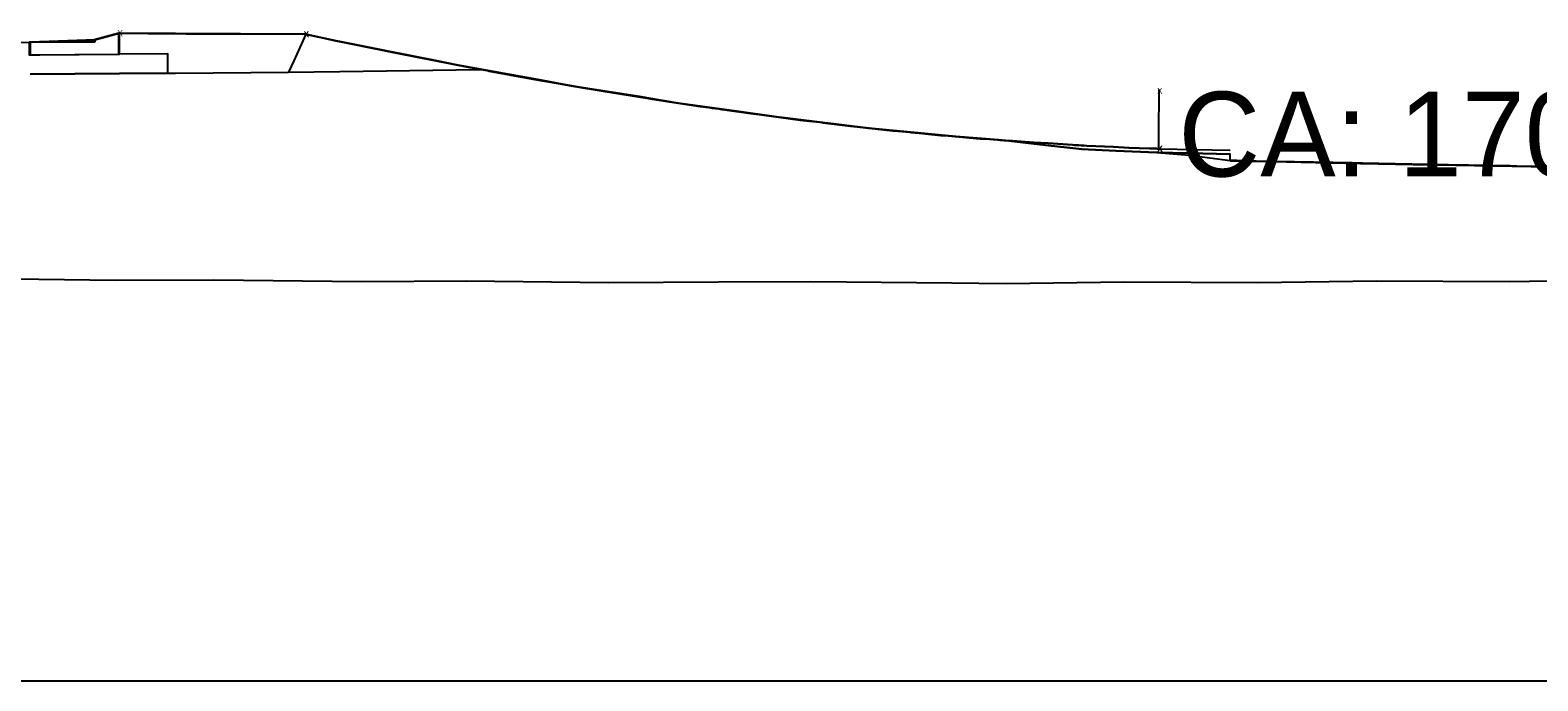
# Model space of a CAD drawing. Extents: x -26 to 303, y -16 to 6048.
# Drawn here: x 183.3 to 243, y 5500 to 5525.8 of the extents above; entities that cross this region are included whole.
import ezdxf

# ---------------------------------------------------------------- set-up
doc = ezdxf.new("R2010")
doc.units = 0
for name, color, linetype in [('CONST_DCH', 7, 'Continuous'), ('CONST_LV3', 7, 'Continuous'), ('DTM_P_FINISHED_GRADE2', 7, 'Continuous'), ('DTM_TEMP_DROP', 7, 'Continuous'), ('DTM_X_GROUND', 7, 'Continuous'), ('TRANS_EOP_PAVED', 7, 'Continuous'), ('X_PROFILES_1', 7, 'Continuous'), ('XS_CELL', 7, 'Continuous'), ('XS_M_SHAPES_EARTHWORK', 7, 'Continuous'), ('XS_P_CONCRETE', 7, 'Continuous'), ('XS_P_GROUND', 7, 'Continuous'), ('XS_P_SHOULDER', 7, 'Continuous'), ('XS_P_SUBGRADE_GRANULAR', 7, 'Continuous'), ('XS_P_SUBGRADE_GRANULAR_B', 7, 'Continuous'), ('XS_SHEET_EW_TX_AREA', 7, 'Continuous')]:
    doc.layers.add(name, color=color, linetype=linetype)

msp = doc.modelspace()

# ---------------------------------------------------------------- linework, layer by layer
at = {"layer": 'CONST_LV3'}
for points in [[(183.216, 5525.326), (183.216, 5524.826), (183.641, 5524.828), (186.773, 5524.85), (186.773, 5525.683), (185.796, 5525.426), (185.794, 5525.342), (183.641, 5525.328), (183.216, 5525.326)], [(186.773, 5525.683), (188.834, 5525.668), (188.862, 5525.668), (188.936, 5525.667), (188.956, 5525.667), (189.005, 5525.667), (189.009, 5525.667), (189.017, 5525.667), (189.153, 5525.666), (189.448, 5525.664), (190.441, 5525.658), (191.471, 5525.651), (194.17, 5525.641)], [(186.773, 5525.683), (188.834, 5525.668), (188.862, 5525.668), (188.936, 5525.667), (188.956, 5525.667), (189.005, 5525.667), (189.009, 5525.667), (189.017, 5525.667), (189.153, 5525.666), (189.448, 5525.664), (190.441, 5525.658), (191.471, 5525.651), (194.17, 5525.641), (195.275, 5525.404), (195.317, 5525.396), (195.435, 5525.372), (195.436, 5525.371), (195.522, 5525.354), (195.524, 5525.354), (195.539, 5525.35), (195.539, 5525.35), (195.898, 5525.275), (195.905, 5525.274), (197.735, 5524.899), (197.803, 5524.888), (200.693, 5524.322), (200.892, 5524.29), (201.015, 5524.266), (201.024, 5524.265), (201.117, 5524.247), (201.124, 5524.246), (201.141, 5524.243), (201.142, 5524.243), (201.437, 5524.187), (201.46, 5524.183), (203.043, 5523.89), (203.196, 5523.866), (205.501, 5523.46), (205.789, 5523.42), (205.915, 5523.398), (205.931, 5523.396), (206.029, 5523.38), (206.042, 5523.378), (206.059, 5523.375), (206.061, 5523.375), (206.081, 5523.372), (206.084, 5523.371), (206.312, 5523.332), (206.344, 5523.328), (207.718, 5523.101), (207.928, 5523.073), (209.834, 5522.776), (210.173, 5522.735), (210.3, 5522.716), (210.324, 5522.713), (210.443, 5522.696), (210.465, 5522.694), (210.485, 5522.691), (210.489, 5522.69), (210.683, 5522.661), (210.72, 5522.657), (211.928, 5522.482), (212.175, 5522.454), (213.797, 5522.236), (214.164, 5522.199), (214.293, 5522.183), (214.323, 5522.18), (214.445, 5522.164), (214.474, 5522.162), (214.663, 5522.138), (214.708, 5522.133), (215.787, 5522), (216.056, 5521.976), (217.474, 5521.816), (217.854, 5521.785), (217.985, 5521.771), (218.021, 5521.769), (218.129, 5521.757), (218.159, 5521.755), (218.177, 5521.754), (218.182, 5521.753), (218.202, 5521.751), (218.208, 5521.751), (218.358, 5521.735), (218.4, 5521.732), (219.379, 5521.632), (219.661, 5521.612), (220.93, 5521.497), (221.314, 5521.475), (221.448, 5521.463), (221.49, 5521.461), (221.62, 5521.45), (221.66, 5521.448), (221.662, 5521.448), (221.662, 5521.448), (221.711, 5521.445), (221.866, 5521.432), (222.202, 5521.414), (223.059, 5521.346), (223.627, 5521.319), (224.601, 5521.252), (224.673, 5521.249), (224.787, 5521.242), (224.85, 5521.24), (224.944, 5521.234), (224.954, 5521.234), (224.968, 5521.233), (225.05, 5521.229), (225.165, 5521.222), (226.224, 5521.176), (226.833, 5521.143), (227.664, 5521.114), (227.764, 5521.109), (227.845, 5521.107), (227.851, 5521.107), (227.927, 5521.104), (227.93, 5521.104), (227.942, 5521.104), (227.943, 5521.104), (227.956, 5521.103), (227.957, 5521.103), (228.018, 5521.101)], [(186.798, 5525.683), (189.017, 5525.667), (194.193, 5525.642), (195.32, 5525.395), (195.539, 5525.35), (200.238, 5524.411), (201.142, 5524.243), (204.774, 5523.588), (206.061, 5523.375), (208.964, 5522.91), (210.465, 5522.693), (212.859, 5522.361), (214.474, 5522.162), (216.512, 5521.923), (218.182, 5521.753), (219.967, 5521.583), (221.66, 5521.448), (221.803, 5521.436), (221.947, 5521.426), (223.523, 5521.24), (224.968, 5521.086), (226.308, 5521.018), (227.943, 5520.957), (229.217, 5520.92), (230.846, 5520.892)], [(188.722, 5524.094), (188.723, 5524.865), (186.798, 5524.85)], [(228.048, 5521.101), (230.838, 5521.039), (230.844, 5521.039), (230.846, 5521.039)]]:
    msp.add_lwpolyline(points, dxfattribs=at)
at = {"layer": 'DTM_P_FINISHED_GRADE2'}
msp.add_lwpolyline([(180.574, 5525.313), (183.26, 5525.327), (184.747, 5525.335), (185.827, 5525.343), (185.828, 5525.379), (185.829, 5525.426), (186.203, 5525.525), (186.798, 5525.683), (187.942, 5525.672), (189.017, 5525.667), (194.193, 5525.642), (195.32, 5525.395), (199.395, 5524.585), (200.238, 5524.411), (203.542, 5523.817), (204.774, 5523.588), (207.504, 5523.153), (208.964, 5522.91), (211.268, 5522.591), (212.859, 5522.361), (214.474, 5522.162), (216.512, 5521.923), (218.182, 5521.753), (219.967, 5521.583), (220.109, 5521.572), (221.803, 5521.436), (221.947, 5521.426), (223.523, 5521.24), (224.968, 5521.086), (226.308, 5521.018), (227.943, 5520.957), (229.23, 5520.84), (230.846, 5520.634), (230.926, 5520.633), (231.048, 5520.63), (231.236, 5520.627), (231.341, 5520.625), (231.628, 5520.619), (231.875, 5520.614), (232.987, 5520.593), (235.685, 5520.54), (235.76, 5520.539), (235.8, 5520.538), (235.99, 5520.534), (236.09, 5520.532), (236.825, 5520.518), (238.697, 5520.482), (238.919, 5520.478), (239.144, 5520.474), (239.719, 5520.462), (239.894, 5520.459), (240.481, 5520.448), (240.941, 5520.439), (241.113, 5520.436), (241.116, 5520.436), (241.217, 5520.434), (241.673, 5520.425), (241.744, 5520.424), (241.75, 5520.423), (242.022, 5520.418), (242.194, 5520.415), (242.385, 5520.411), (242.508, 5520.409), (242.971, 5520.4), (243.02, 5520.399), (243.352, 5520.393)], dxfattribs=at)
at = {"layer": 'DTM_X_GROUND'}
for points in [[(183.26, 5525.327), (184.748, 5525.383), (185.829, 5525.426), (186.462, 5525.595), (186.798, 5525.683), (187.942, 5525.672), (189.017, 5525.667), (194.193, 5525.642), (195.32, 5525.395), (199.395, 5524.585), (200.238, 5524.411), (203.542, 5523.817), (204.774, 5523.588), (207.504, 5523.153), (207.795, 5523.104), (208.964, 5522.91), (211.268, 5522.591), (212.859, 5522.361), (213.73, 5522.253), (214.474, 5522.162), (216.512, 5521.923), (216.908, 5521.883), (217.404, 5521.832), (218.182, 5521.753), (219.967, 5521.583), (220.109, 5521.572), (221.803, 5521.436), (221.947, 5521.426), (223.523, 5521.24), (224.968, 5521.086), (226.308, 5521.018), (227.322, 5520.98), (227.943, 5520.957), (229.23, 5520.84), (230.846, 5520.634), (230.926, 5520.633), (231.048, 5520.63), (231.107, 5520.629), (231.236, 5520.627), (231.341, 5520.625), (231.628, 5520.619), (231.644, 5520.619), (231.891, 5520.614), (231.929, 5520.613), (232.674, 5520.599), (234.47, 5520.564), (234.819, 5520.557), (235.685, 5520.54), (235.76, 5520.539), (235.8, 5520.538), (235.99, 5520.534), (236.251, 5520.529), (236.351, 5520.527), (237.01, 5520.515), (237.484, 5520.506), (237.866, 5520.498), (238.697, 5520.482), (238.919, 5520.478), (238.935, 5520.478), (239.111, 5520.474), (239.686, 5520.463), (239.719, 5520.462), (239.76, 5520.462), (239.902, 5520.459), (240.304, 5520.451), (240.361, 5520.45), (240.448, 5520.448), (240.481, 5520.448), (240.855, 5520.441), (240.996, 5520.438), (241.083, 5520.436), (241.113, 5520.436), (241.116, 5520.436), (241.49, 5520.428), (241.592, 5520.427), (241.631, 5520.426), (241.712, 5520.424), (241.718, 5520.424), (241.75, 5520.423), (242.022, 5520.418), (242.162, 5520.416), (242.266, 5520.414), (242.353, 5520.412), (242.385, 5520.411), (242.761, 5520.404), (242.884, 5520.402), (242.9, 5520.401), (242.987, 5520.4), (243.02, 5520.399), (243.352, 5520.393)], [(180.548, 5515.965), (186.639, 5515.888), (190.547, 5515.908), (196.408, 5515.838), (200.547, 5515.859), (206.192, 5515.795), (210.547, 5515.818), (214.225, 5515.837), (219.816, 5515.78), (221.959, 5515.757), (226.64, 5515.827), (231.941, 5515.797), (236.65, 5515.869), (241.923, 5515.837), (246.661, 5515.911)]]:
    msp.add_lwpolyline(points, dxfattribs=at)
at = {"layer": 'XS_CELL'}
msp.add_line((150, 5500), (300, 5500), dxfattribs=at)
at = {"layer": 'XS_M_SHAPES_EARTHWORK'}
msp.add_lwpolyline([(183.26, 5524.056), (186.798, 5524.079), (188.722, 5524.094), (189.017, 5524.097), (193.505, 5524.14), (195.539, 5524.163), (201.08, 5524.238), (201.142, 5524.238), (201.166, 5524.239), (204.774, 5523.588), (203.542, 5523.817), (200.238, 5524.411), (199.395, 5524.585), (195.32, 5525.395), (194.193, 5525.642), (189.017, 5525.667), (187.942, 5525.672), (186.798, 5525.683), (186.462, 5525.595), (185.829, 5525.426), (184.748, 5525.383), (183.26, 5525.327)], dxfattribs=at)
for points in [[(206.061, 5523.375), (208.964, 5522.91), (207.795, 5523.104), (207.504, 5523.153), (204.774, 5523.588)], [(210.465, 5522.693), (212.859, 5522.361), (211.268, 5522.591), (208.964, 5522.91)], [(219.967, 5521.583), (220.109, 5521.572), (221.803, 5521.436), (221.66, 5521.448)], [(227.943, 5520.957), (229.23, 5520.84), (230.846, 5520.634), (230.846, 5520.892), (229.217, 5520.92)]]:
    msp.add_lwpolyline(points, close=True, dxfattribs=at)
at = {"layer": 'XS_P_CONCRETE'}
msp.add_lwpolyline([(183.26, 5525.327), (183.26, 5524.827), (186.798, 5524.85), (186.798, 5525.683), (185.829, 5525.426), (185.827, 5525.343), (183.26, 5525.327)], dxfattribs=at)
at = {"layer": 'XS_P_GROUND'}
for points in [[(228.018, 5521.101), (227.957, 5521.103), (227.956, 5521.103), (227.943, 5521.104), (227.942, 5521.104), (227.93, 5521.104), (227.927, 5521.104), (227.851, 5521.107), (227.845, 5521.107), (227.764, 5521.109), (227.664, 5521.114), (226.833, 5521.143), (226.224, 5521.176), (225.165, 5521.222), (225.05, 5521.229), (224.968, 5521.233), (224.954, 5521.234), (224.944, 5521.234), (224.85, 5521.24), (224.787, 5521.242), (224.673, 5521.249), (224.601, 5521.252), (223.627, 5521.319), (223.059, 5521.346), (222.202, 5521.414), (221.866, 5521.432), (221.711, 5521.445), (221.662, 5521.448), (221.662, 5521.448), (221.66, 5521.448), (221.62, 5521.45), (221.49, 5521.461), (221.448, 5521.463), (221.314, 5521.475), (220.93, 5521.497), (219.661, 5521.612), (219.379, 5521.632), (218.4, 5521.732), (218.358, 5521.735), (218.208, 5521.751), (218.202, 5521.751), (218.182, 5521.753), (218.177, 5521.754), (218.159, 5521.755), (218.129, 5521.757), (218.021, 5521.769), (217.985, 5521.771), (217.854, 5521.785), (217.474, 5521.816), (216.056, 5521.976), (215.787, 5522), (214.708, 5522.133), (214.663, 5522.138), (214.474, 5522.162), (214.445, 5522.164), (214.323, 5522.18), (214.293, 5522.183), (214.164, 5522.199), (213.797, 5522.236), (212.175, 5522.454), (211.928, 5522.482), (210.72, 5522.657), (210.683, 5522.661), (210.489, 5522.69), (210.485, 5522.691), (210.465, 5522.694), (210.443, 5522.696), (210.324, 5522.713), (210.3, 5522.716), (210.173, 5522.735), (209.834, 5522.776), (207.928, 5523.073), (207.718, 5523.101), (206.344, 5523.328), (206.312, 5523.332), (206.084, 5523.371), (206.081, 5523.372), (206.061, 5523.375), (206.059, 5523.375), (206.042, 5523.378), (206.029, 5523.38), (205.931, 5523.396), (205.915, 5523.398), (205.789, 5523.42), (205.501, 5523.46), (203.196, 5523.866), (203.043, 5523.89), (201.46, 5524.183), (201.437, 5524.187), (201.142, 5524.243), (201.141, 5524.243), (201.124, 5524.246), (201.117, 5524.247), (201.024, 5524.265), (201.015, 5524.266), (200.892, 5524.29), (200.693, 5524.322), (197.803, 5524.888), (197.735, 5524.899), (195.905, 5525.274), (195.898, 5525.275), (195.539, 5525.35), (195.539, 5525.35), (195.524, 5525.354), (195.522, 5525.354), (195.436, 5525.371), (195.435, 5525.372), (195.317, 5525.396), (195.275, 5525.404), (194.17, 5525.641)], [(230.846, 5520.892), (229.217, 5520.92), (227.943, 5520.957), (226.308, 5521.018), (224.968, 5521.086), (223.523, 5521.24), (221.947, 5521.426), (221.803, 5521.436), (221.66, 5521.448), (219.967, 5521.583), (218.182, 5521.753), (216.512, 5521.923), (214.474, 5522.162), (212.859, 5522.361), (210.465, 5522.693), (208.964, 5522.91), (206.061, 5523.375), (204.774, 5523.588), (201.142, 5524.243), (200.238, 5524.411), (195.539, 5525.35), (195.32, 5525.395), (194.193, 5525.642)], [(228.018, 5521.101), (228.018, 5521.174), (228.022, 5521.7), (228.032, 5523.395), (228.032, 5523.398), (228.033, 5523.436), (228.048, 5523.436)], [(228.048, 5521.101), (230.838, 5521.039), (230.844, 5521.039), (230.846, 5521.039)], [(243.303, 5520.394), (242.848, 5520.402), (242.213, 5520.415), (241.95, 5520.42), (241.577, 5520.427), (241.569, 5520.427), (240.941, 5520.439), (240.306, 5520.451), (239.494, 5520.467), (238.697, 5520.482), (236.09, 5520.532), (235.95, 5520.535), (235.685, 5520.54), (231.875, 5520.614), (231.524, 5520.621), (231.114, 5520.629), (230.846, 5520.634)], [(230.846, 5520.621), (232.293, 5520.593), (233.068, 5520.578), (236.016, 5520.521), (238.102, 5520.48), (238.784, 5520.467), (239.026, 5520.463), (242.779, 5520.391), (243.136, 5520.384)]]:
    msp.add_lwpolyline(points, dxfattribs=at)
at = {"layer": 'XS_P_SHOULDER'}
msp.add_lwpolyline([(186.798, 5525.683), (189.017, 5525.667), (194.193, 5525.642)], dxfattribs=at)
at = {"layer": 'XS_P_SUBGRADE_GRANULAR'}
for points in [[(186.798, 5524.079), (183.26, 5524.056)], [(188.722, 5524.094), (186.798, 5524.079)]]:
    msp.add_lwpolyline(points, dxfattribs=at)
at = {"layer": 'XS_P_SUBGRADE_GRANULAR_B'}
for points in [[(194.193, 5525.642), (193.711, 5524.589), (193.505, 5524.14)], [(188.722, 5524.094), (189.017, 5524.097), (193.505, 5524.14)], [(193.505, 5524.14), (195.539, 5524.163), (201.08, 5524.238), (201.142, 5524.238), (201.166, 5524.239)]]:
    msp.add_lwpolyline(points, dxfattribs=at)

# ---------------------------------------------------------------- texts
at = {"layer": 'CONST_DCH'}
for p in [(227.939, 5520.981), (227.969, 5520.981)]:
    msp.add_text('X', height=0.24, dxfattribs=at).set_placement(p)
at = {"layer": 'DTM_TEMP_DROP'}
for p in [(227.939, 5520.981), (227.969, 5520.981)]:
    msp.add_text('X', height=0.24, dxfattribs=at).set_placement(p)
at = {"layer": 'TRANS_EOP_PAVED'}
msp.add_text('X', height=0.24, dxfattribs=at).set_placement((227.953, 5523.275))
at = {"layer": 'X_PROFILES_1'}
msp.add_text('X', height=0.24, dxfattribs=at).set_placement((194.092, 5525.521))
at = {"layer": 'XS_P_GROUND'}
for p in [(186.719, 5525.563), (194.115, 5525.522)]:
    msp.add_text('X', height=0.24, dxfattribs=at).set_placement(p)
at = {"layer": 'XS_SHEET_EW_TX_AREA'}
msp.add_text('CA: 170.03 SF', height=3.36, dxfattribs=at).set_placement((228.794, 5520))

doc.saveas('drawing.dxf')
